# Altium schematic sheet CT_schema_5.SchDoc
size 277 x 170 mm
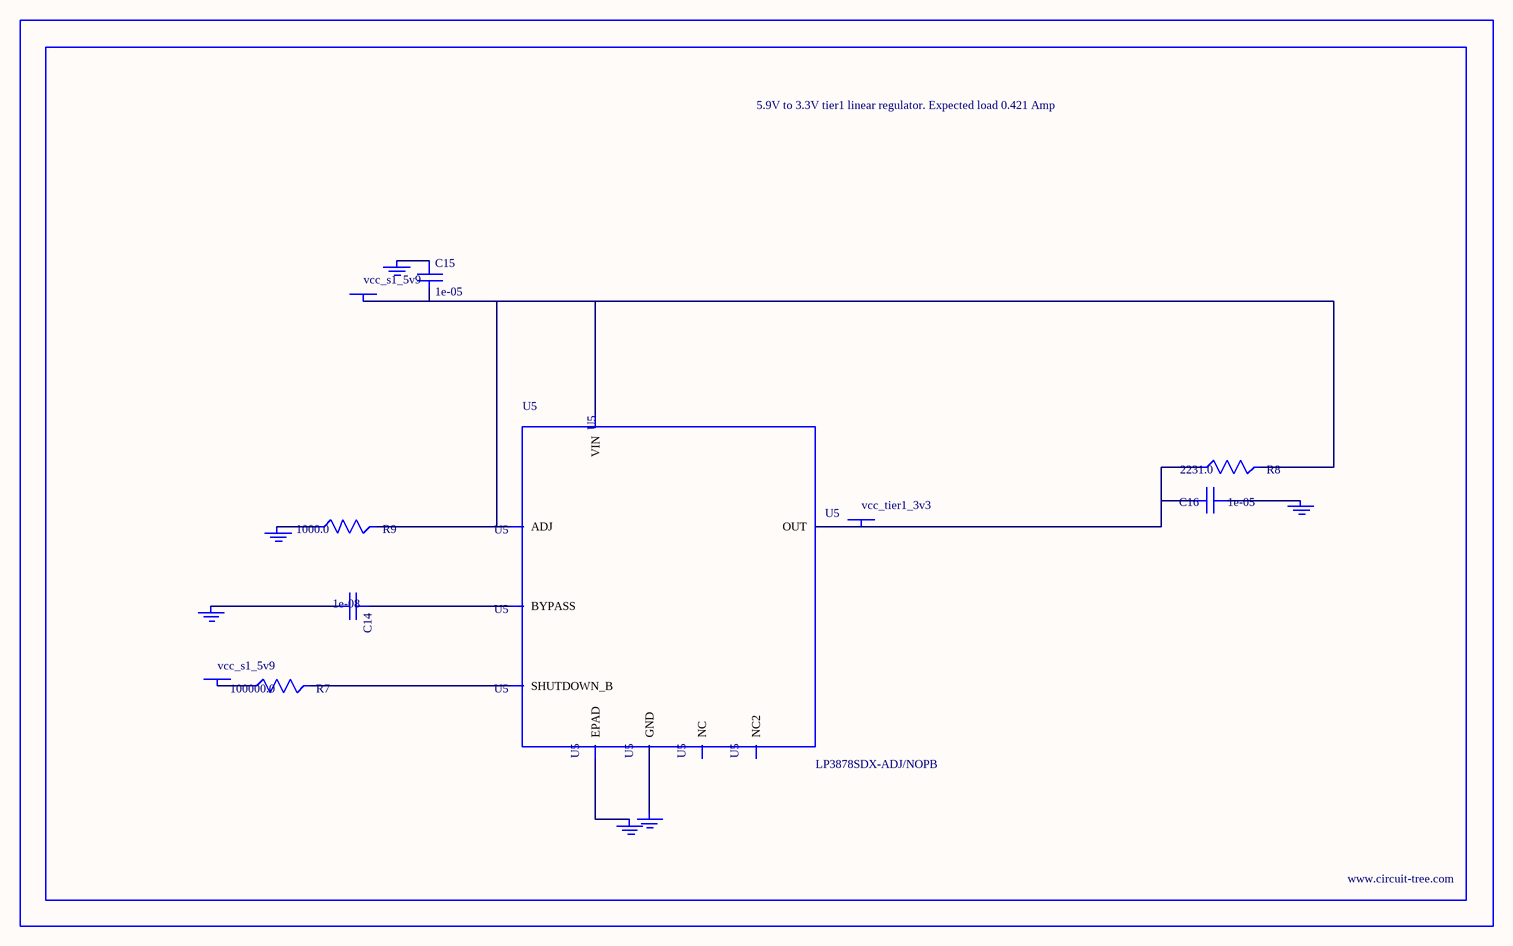
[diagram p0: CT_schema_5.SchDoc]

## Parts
BORDER4  (no value)
C14  1e-08  [C0402]
C15  1e-05  [C1206]
C16  1e-05  [C1210]
GND_INSTANCE_4_0  (no value)
GND_INSTANCE_4_1  (no value)
GND_INSTANCE_4_2  (no value)
GND_INSTANCE_4_3  (no value)
GND_INSTANCE_4_4  (no value)
GND_INSTANCE_4_5  (no value)
POWER_INSTANCE_4_0  vcc_s1_5v9
POWER_INSTANCE_4_1  vcc_s1_5v9
POWER_INSTANCE_4_2  vcc_tier1_3v3
R7  100000.0  [R0603]
R8  2231.0  [R0603]
R9  1000.0  [R0603]
U5  LP3878SDX-ADJ/NOPB  [WSON-8]

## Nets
NetC14_1: C14.1 U5.1(BYPASS)
NetC14_2: C14.2 GND_INSTANCE_4_0.0(GND)
NetC15_1: C15.1 GND_INSTANCE_4_1.0(GND)
NetC15_2: C15.2 POWER_INSTANCE_4_0.0(PWR) R8.2 R9.2 U5.4(VIN) U5.6(ADJ)
NetC16_1: C16.1 GND_INSTANCE_4_2.0(GND)
NetC16_2: C16.2 POWER_INSTANCE_4_2.0(PWR) R8.1 U5.5(OUT)
NetGND_INSTANCE_4_3_0: GND_INSTANCE_4_3.0(GND) R9.1
NetGND_INSTANCE_4_4_0: GND_INSTANCE_4_4.0(GND) U5.PAD(EPAD)
NetGND_INSTANCE_4_5_0: GND_INSTANCE_4_5.0(GND) U5.3(GND)
NetPOWER_INSTANCE_4_1_0: POWER_INSTANCE_4_1.0(PWR) R7.1
NetR7_2: R7.2 U5.8(SHUTDOWN_B)

Not connected (* = marked no-connect by the designer): U5 2(NC) 7(NC2)

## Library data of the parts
BORDER4 = BORDER_PAGE4
C14 = C0402C103K3RAC
C15 = C1206C106K3RACTU
C16 = GRM32DR61E106MA12L
GND_INSTANCE_4_0-GND_INSTANCE_4_5 = GND
POWER_INSTANCE_4_0-POWER_INSTANCE_4_2 = PWR
R7 = RC0603JR-07100KL
R8 = R8
R9 = RC0603JR-071KL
